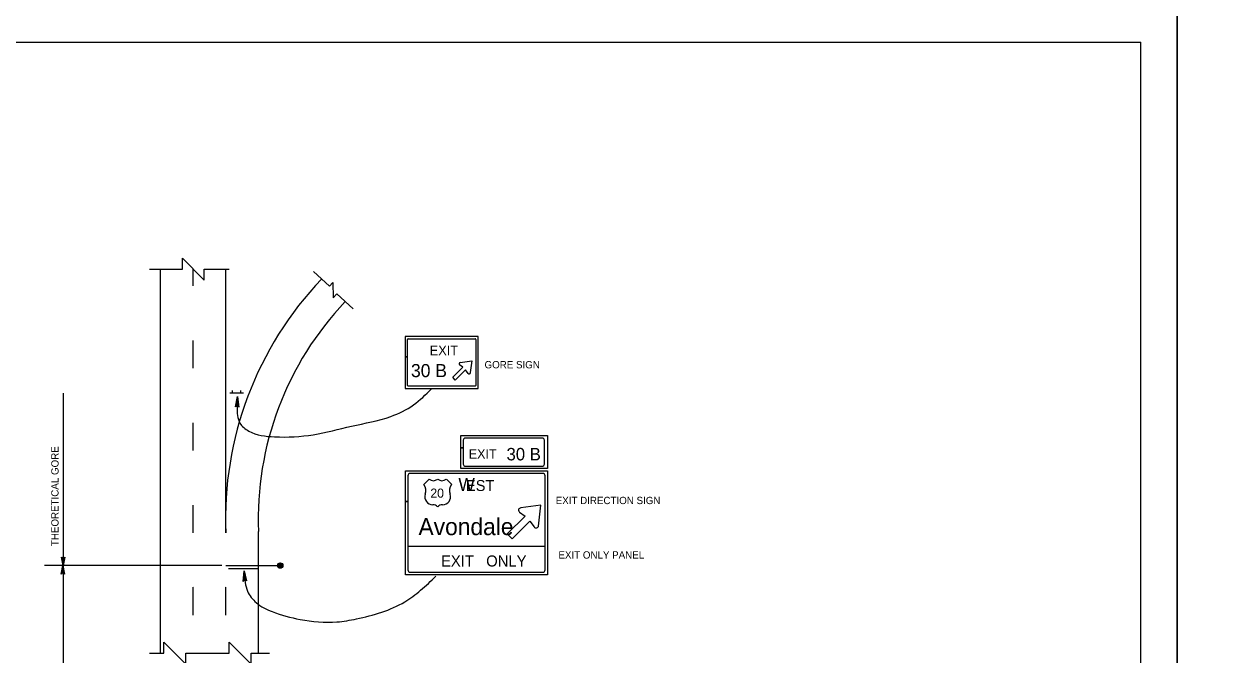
# Model space of a CAD drawing. Extents: x 640994 to 644422, y 298458 to 299646.
# Drawn here: x 642202.5 to 642696.3, y 298785.1 to 299044.1 of the extents above; entities that cross this region are included whole.
import ezdxf

# ---------------------------------------------------------------- set-up
doc = ezdxf.new("R2010")
doc.units = 0
for name, color, linetype in [('1', 7, 'Continuous'), ('2', 7, 'Continuous'), ('XCS-GRID-MIN', 7, 'Continuous')]:
    doc.layers.add(name, color=color, linetype=linetype)

msp = doc.modelspace()

# ---------------------------------------------------------------- linework, layer by layer
at = {"layer": '1'}
for p in [(641875.31, 299036.63), (642661.31, 298472.63)]:
    msp.add_line(p, (642661.31, 299036.63), dxfattribs=at)
at = {"layer": '2'}
for p, q in [((642254.06, 298943.5), (642267.56, 298943.5)), ((642258.56, 298785.75), (642258.56, 298943.5)), ((642271.94, 298936.63), (642271.94, 298943.63)), ((642276.56, 298943.5), (642286.81, 298943.5)), ((642285.44, 298841.75), (642285.44, 298943.5)), ((642321.44, 298942.5), (642327.94, 298936.5)), ((642271.94, 298936.63), (642271.94, 298936.63)), ((642331.06, 298933.38), (642337.69, 298927.13)), ((642271.94, 298914.13), (642271.94, 298914.13)), ((642271.94, 298902.88), (642271.94, 298914.13)), ((642389.06, 298915.88), (642359.06, 298915.88)), ((642359.06, 298915.88), (642359.06, 298907.46)), ((642360.06, 298907.46), (642360.06, 298914.63)), ((642360.31, 298914.88), (642387.81, 298914.88)), ((642388.06, 298914.63), (642388.06, 298895.75)), ((642389.06, 298894.5), (642389.06, 298915.88)), ((642360.06, 298907.46), (642359.06, 298907.46)), ((642359.06, 298907.46), (642359.06, 298894.5)), ((642359.06, 298907.46), (642360.06, 298907.46)), ((642360.06, 298895.75), (642360.06, 298907.46)), ((642271.94, 298902.88), (642271.94, 298902.88)), ((642378.67, 298899.07), (642382.8, 298903.19)), ((642383.92, 298902.19), (642379.67, 298897.94)), ((642382.8, 298903.19), (642381.42, 298904.19)), ((642381.67, 298905.19), (642386.42, 298905.82)), ((642384.92, 298900.69), (642383.92, 298902.19)), ((642386.42, 298905.82), (642385.8, 298901.07)), ((642379.67, 298897.94), (642378.67, 298899.07)), ((642218.56, 298892.5), (642218.56, 298821.75)), ((642292.69, 298892.5), (642287.06, 298892.5)), ((642288.19, 298892.5), (642288.19, 298893.63)), ((642291.56, 298892.5), (642291.56, 298893.63)), ((642359.06, 298894.5), (642389.06, 298894.5)), ((642387.81, 298895.5), (642360.31, 298895.5)), ((642271.94, 298880.38), (642271.94, 298880.38)), ((642271.94, 298869), (642271.94, 298880.38)), ((642381.94, 298870.08), (642381.94, 298875.13)), ((642381.94, 298875.13), (642417.56, 298875.13)), ((642382.94, 298873.38), (642382.94, 298870.08)), ((642415.69, 298874.13), (642383.56, 298874.13)), ((642416.31, 298863.38), (642416.31, 298873.38)), ((642417.56, 298875.13), (642417.56, 298861.63)), ((642271.94, 298869), (642271.94, 298869)), ((642382.94, 298870.08), (642381.94, 298870.08)), ((642381.94, 298861.63), (642381.94, 298870.08)), ((642381.94, 298870.08), (642382.94, 298870.08)), ((642382.94, 298870.08), (642382.94, 298863.38)), ((642383.56, 298862.63), (642415.69, 298862.63)), ((642359.19, 298848.02), (642359.19, 298860.63)), ((642359.19, 298860.63), (642417.56, 298860.63)), ((642415.56, 298859.63), (642361.19, 298859.63)), ((642366.69, 298855), (642368.94, 298857.25)), ((642376.06, 298857.25), (642378.19, 298855)), ((642417.56, 298861.63), (642381.94, 298861.63)), ((642416.56, 298820), (642416.56, 298858.63)), ((642417.56, 298860.63), (642417.56, 298818)), ((642360.19, 298848.02), (642359.19, 298848.02)), ((642359.19, 298818), (642359.19, 298848.02)), ((642359.19, 298848.02), (642360.19, 298848.02)), ((642372.44, 298851.5), (642372.44, 298851.5)), ((642372.44, 298851.5), (642372.44, 298851.5)), ((642372.44, 298851.5), (642372.44, 298851.5)), ((642372.44, 298851.5), (642372.44, 298851.5)), ((642372.44, 298851.5), (642372.44, 298851.5)), ((642372.44, 298851.5), (642372.44, 298851.5)), ((642374.69, 298849.25), (642374.69, 298849.25)), ((642377.69, 298850), (642377.69, 298850)), ((642271.94, 298846.5), (642271.94, 298846.5)), ((642271.94, 298835.25), (642271.94, 298846.5)), ((642285.44, 298846.5), (642285.44, 298846.5)), ((642285.44, 298835.25), (642285.44, 298846.5)), ((642370.44, 298846.75), (642370.44, 298846.75)), ((642374.44, 298846.75), (642374.44, 298846.75)), ((642406.06, 298843.63), (642408.44, 298842)), ((642406.06, 298843.63), (642408.44, 298842)), ((642414.81, 298846.5), (642406.56, 298845.5)), ((642414.81, 298846.5), (642406.56, 298845.5)), ((642413.81, 298838), (642414.81, 298846.5)), ((642413.81, 298838), (642414.81, 298846.5)), ((642408.44, 298842), (642401.06, 298834.75)), ((642408.44, 298842), (642401.06, 298834.75)), ((642403.06, 298832.75), (642410.31, 298840)), ((642403.06, 298832.75), (642410.31, 298840)), ((642410.31, 298840), (642412.06, 298837.63)), ((642410.31, 298840), (642412.06, 298837.63)), ((642271.94, 298835.25), (642271.94, 298835.25)), ((642285.44, 298835.25), (642285.44, 298835.25)), ((642298.81, 298785.75), (642298.81, 298835.75)), ((642401.06, 298834.75), (642403.06, 298832.75)), ((642401.06, 298834.75), (642403.06, 298832.75)), ((642218.56, 298821.75), (642217.94, 298825.25)), ((642217.94, 298825.25), (642218.19, 298825.13)), ((642218.44, 298825), (642218.19, 298825.13)), ((642218.19, 298825.13), (642218.56, 298821.75)), ((642218.56, 298821.75), (642218.44, 298825)), ((642219.19, 298825.25), (642218.56, 298821.75)), ((642218.56, 298821.75), (642219.06, 298825.13)), ((642218.81, 298825), (642218.56, 298821.75)), ((642219.06, 298825.13), (642218.81, 298825)), ((642219.06, 298825.13), (642219.19, 298825.25)), ((642306.81, 298821.63), (642307.94, 298822.75)), ((642307.94, 298822.75), (642306.94, 298822.38)), ((642307.44, 298821), (642307.56, 298822.5)), ((642307.56, 298822.5), (642307.94, 298820.88)), ((642307.94, 298820.88), (642307.94, 298822.75)), ((642307.94, 298822.75), (642308.31, 298821.13)), ((642308.31, 298821.13), (642308.31, 298822.5)), ((642308.31, 298822.5), (642308.56, 298821.63)), ((642283.81, 298821.75), (642210.94, 298821.75)), ((642217.81, 298818.25), (642218.44, 298821.75)), ((642217.94, 298818.38), (642217.81, 298818.25)), ((642218.44, 298821.75), (642217.94, 298818.38)), ((642217.94, 298818.38), (642218.19, 298818.5)), ((642218.19, 298818.5), (642218.44, 298821.75)), ((642218.44, 298821.75), (642218.56, 298818.5)), ((642218.81, 298818.38), (642218.44, 298821.75)), ((642218.44, 298821.75), (642219.06, 298818.25)), ((642218.56, 298821.75), (642218.56, 298723.25)), ((642218.56, 298818.5), (642218.81, 298818.38)), ((642219.06, 298818.25), (642218.81, 298818.38)), ((642285.44, 298821.75), (642307.81, 298821.75)), ((642286.56, 298820.63), (642298.81, 298820.63)), ((642308.56, 298822.25), (642306.81, 298821.63)), ((642307.06, 298821.13), (642307.06, 298822.25)), ((642307.06, 298822.25), (642307.44, 298821)), ((642307.69, 298820.88), (642308.56, 298822.25)), ((642308.56, 298821.63), (642307.69, 298820.88)), ((642307.81, 298821.75), (642307.81, 298821.75)), ((642417.56, 298818), (642359.19, 298818)), ((642361.19, 298819), (642415.56, 298819)), ((642271.94, 298813), (642271.94, 298813)), ((642271.94, 298812.88), (642271.94, 298812.88)), ((642271.94, 298801.38), (642271.94, 298812.88)), ((642285.44, 298813), (642285.44, 298813)), ((642285.44, 298812.88), (642285.44, 298812.88)), ((642285.44, 298801.38), (642285.44, 298812.88)), ((642271.94, 298801.63), (642271.94, 298801.63)), ((642271.94, 298801.38), (642271.94, 298801.38)), ((642285.44, 298801.63), (642285.44, 298801.63)), ((642285.44, 298801.38), (642285.44, 298801.38)), ((642254.06, 298785.75), (642259.94, 298785.75)), ((642268.94, 298785.75), (642286.81, 298785.75)), ((642295.81, 298785.75), (642303.31, 298785.75))]:
    msp.add_line(p, q, dxfattribs=at)
for points in [[(642267.56, 298943.5), (642267.56, 298948), (642276.56, 298939), (642276.56, 298943.5)], [(642327.94, 298936.5), (642329.31, 298938), (642329.56, 298931.75), (642331.06, 298933.38)], [(642289.56, 298887.13), (642289.81, 298887.25), (642290.19, 298891.13), (642289.56, 298887.13), (642289.31, 298886.88), (642290.19, 298891.13), (642290.31, 298887.25), (642290.56, 298887.13), (642290.19, 298891.13), (642290.69, 298886.75), (642290.56, 298887.13)], [(642360.19, 298858.63), (642360.19, 298848.02)], [(642360.19, 298848.02), (642360.19, 298820)], [(642360.19, 298829.75), (642416.56, 298829.75)], [(642292.81, 298815.5), (642292.94, 298815.63), (642292.94, 298819.63), (642292.81, 298815.5), (642292.56, 298815.25), (642292.94, 298819.63), (642293.44, 298815.75), (642293.69, 298815.63), (642292.94, 298819.63), (642293.94, 298815.5), (642293.69, 298815.63)], [(642259.94, 298785.75), (642259.94, 298790.25), (642268.94, 298781.25), (642268.94, 298785.75)], [(642286.81, 298785.75), (642286.81, 298790.25), (642295.81, 298781.25), (642295.81, 298785.75)]]:
    msp.add_lwpolyline(points, dxfattribs=at)
msp.add_circle((642307.75, 298821.78), 1.12, dxfattribs=at)
for centre, radius, start, end in [((642428.39, 298840.74), 143.14, 136.4155, 182.2116), ((642428.39, 298840.74), 129.7, 136.4155, 182.2116), ((642360.31, 298914.63), 0.25, 90, 180), ((642387.81, 298914.63), 0.25, 0, 90), ((642381.79, 298904.65), 0.559, 94.8591, 235.5247), ((642385.35, 298901.05), 0.559, 213.2476, 357.1543), ((642360.31, 298895.75), 0.25, 180, 270), ((642387.81, 298895.75), 0.25, 270, 0), ((642361.19, 298858.63), 1, 90, 180), ((642370.69, 298859.55), 2.93, 233.136, 306.864), ((642374.2, 298859.55), 2.93, 233.136, 306.864), ((642415.56, 298858.63), 1, 0, 90), ((642363.02, 298852.45), 4.55, 341.8289, 34.5747), ((642381.86, 298852.45), 4.55, 145.4253, 198.1711), ((642370.44, 298849.99), 3.26, 161.452, 269.9953), ((642374.45, 298849.99), 3.26, 270.0047, 18.548), ((642370.43, 298843.97), 2.76, 43.7275, 90), ((642374.45, 298843.97), 2.76, 90, 136.2725), ((642406.66, 298844.5), 0.978, 94.8565, 235.522), ((642406.66, 298844.5), 0.978, 94.8565, 235.522), ((642412.89, 298838.2), 0.978, 213.2449, 357.1516), ((642412.89, 298838.2), 0.978, 213.2449, 357.1516), ((642361.19, 298820), 1, 180, 270), ((642415.56, 298820), 1, 270, 0)]:
    msp.add_arc(centre, radius, start, end, dxfattribs=at)
for centre, major_axis, start_param, end_param in [((642383.62, 298873.28), (0, -0.792), 3.141593, 4.712389), ((642415.65, 298873.28), (0, 0.792), 4.712389, 6.283185), ((642383.62, 298863.43), (0, -0.792), 4.712389, 6.283185), ((642415.65, 298863.43), (0, 0.792), 3.141593, 4.712389)]:
    msp.add_ellipse(centre, major_axis=major_axis, ratio=0.827467, start_param=start_param, end_param=end_param, dxfattribs=at)
for points in [[(642290.19, 298891.13), (642290.06, 298886.75), (642291.19, 298880.25), (642294.81, 298877), (642305.44, 298874.63), (642321.31, 298875.5), (642337.06, 298879), (642353.19, 298883), (642362.56, 298887.75), (642369.81, 298894.25)], [(642292.94, 298819.63), (642293.31, 298814.75), (642294.31, 298811.25), (642297.94, 298806.5), (642304.44, 298802.88), (642315.94, 298799.63), (642331.06, 298798.63), (642339.06, 298799.88), (642349.44, 298802.63), (642358.94, 298806.88), (642365.44, 298811.63), (642371.69, 298817.38)]]:
    msp.add_spline(points, degree=3, dxfattribs=at)
at = {"layer": 'XCS-GRID-MIN'}
for points in [[(641835.31, 299051.63), (642676.31, 299051.63), (642676.31, 298457.63), (641835.31, 298457.63)], [(642676.31, 299051.63), (643517.31, 299051.63), (643517.31, 298457.63), (642676.31, 298457.63)]]:
    msp.add_lwpolyline(points, close=True, dxfattribs=at)

# ---------------------------------------------------------------- texts
at = {"layer": '2'}
for s, height, p in [('EXIT', 3.917, (642369.19, 298908.13)), ('30 B ', 5.375, (642361.48, 298899.14)), ('GORE SIGN', 3, (642391.69, 298902.75)), ('EXIT', 3.875, (642385.17, 298865.67)), ('30 B', 5.125, (642400.73, 298864.95)), ('W', 5.38, (642380.94, 298852.38)), ('EST', 4.5, (642384.06, 298852.38)), ('20', 3.75, (642369.44, 298849.63)), ('EXIT DIRECTION SIGN', 3, (642420.94, 298847)), ('EXIT ONLY PANEL', 3, (642422.06, 298824.63)), ('EXIT   ONLY', 4.5457, (642373.81, 298821.38))]:
    msp.add_text(s, height=height, dxfattribs=at).set_placement(p)
for s, height, rotation, p in [('THEORETICAL GORE', 3, 90, (642216.69, 298829.75)), ('Avondale', 7, 359.9998, (642364.56, 298834.25))]:
    msp.add_text(s, height=height, rotation=rotation, dxfattribs=at).set_placement(p)

doc.saveas('drawing.dxf')
